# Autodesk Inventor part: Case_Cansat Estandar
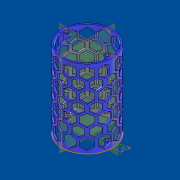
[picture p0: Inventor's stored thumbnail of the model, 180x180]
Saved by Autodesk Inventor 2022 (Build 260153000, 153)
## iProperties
Created: 2022-05
Part Number: Case_Cansat Estandar
Material: Genérico
Document SubType Name: Modeling
Designer: pined
Density: 1 g/cm^3
Appearance: Valor por defecto
Author: pined
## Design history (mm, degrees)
sketch "Boceto1"
  geometry: C1 r 32.5 at (0, 0); C2 r 30.5 at (0, 0); 1 further point
  constraints: 2 centre point, 2 coincident
  dimensions: "d0" = 65 diameter of C1; "d1" = 61 diameter of C2
extrude "Extrusión1" new body sketch "Boceto1" distance "d2" = 100; taper "d3" = 0 deg
node "Plano de trabajo1"
sketch "Boceto3"
  geometry: L1 (57, 0)-(53.5, -6.062); L2 (53.5, -6.062)-(46.5, -6.062); L3 (46.5, -6.062)-(43, 0); L4 (43, 0)-(46.5, 6.062); L5 (46.5, 6.062)-(53.5, 6.062); L6 (53.5, 6.062)-(57, 0); L7 (69.196, 0)-(72.696, 6.062); L8 (72.696, 6.062)-(79.696, 6.062); L9 (79.696, 6.062)-(83.196, 0); L10 (83.196, 0)-(79.696, -6.062); L11 (79.696, -6.062)-(72.696, -6.062); L12 (72.696, -6.062)-(69.196, 0); L13 (20.304, 6.062)-(16.804, 0); L14 (16.804, 0)-(20.304, -6.062); L15 (27.304, 6.062)-(20.304, 6.062); L16 (30.804, 0)-(27.304, 6.062); L17 (27.304, -6.062)-(30.804, 0); L18 (20.304, -6.062)-(27.304, -6.062); L19 (43, 0)-(46.5, -6.062); L20 (46.5, 6.062)-(43, 0); L21 (53.5, 6.062)-(46.5, 6.062); L22 (57, 0)-(53.5, 6.062); L23 (53.5, -6.062)-(57, 0); L24 (46.5, -6.062)-(53.5, -6.062); 5 further points
  constraints: 48 end point, 13 other
extrude "Extrusión2" cut sketch "Boceto3" distance "d29" = 10; taper "d30" = 0 deg
pattern_circular "Patrón circular1" dims angle "d32" = 360 deg
sketch "Boceto4"
  geometry: L1 (0, 0)-(-35, 0); L2 (0, 0)-(-36.309, -9.729); A1 r 32.5 centre (0, 0) between (-32.5, 0) and (-31.393, -8.412) reference; 1 further point
  constraints: 4 end point, 2 point on circle, 2 point on line, 1 horizontal
  dimensions: "d34" = 15 deg angle of L1 L2
node "Plano de trabajo3"
sketch "Boceto7"
  geometry: L1 (27.304, 2.408)-(20.304, 2.408) reference; L2 (20.304, -2.408)-(27.304, -2.408) reference; L3 (97, 0)-(93, -6.928); L4 (93, -6.928)-(85, -6.928); L5 (85, -6.928)-(81, 0); L6 (81, 0)-(85, 6.928); L7 (85, 6.928)-(93, 6.928); L8 (93, 6.928)-(97, 0); L9 (100, -32.5)-(100, 32.5) reference; L10 (19, 0)-(15, -6.928); L11 (15, -6.928)-(7, -6.928); L12 (7, -6.928)-(3, 0); L13 (3, 0)-(7, 6.928); L14 (7, 6.928)-(15, 6.928); L15 (15, 6.928)-(19, 0); L16 (0, 59.406)-(0, -64.57) reference; L17 (29, 0)-(33, 6.928); L18 (33, 6.928)-(41, 6.928); L19 (41, 6.928)-(45, 0); L20 (45, 0)-(41, -6.928); L21 (41, -6.928)-(33, -6.928); L22 (33, -6.928)-(29, 0); L23 (71, 0)-(67, -6.928); L24 (67, -6.928)-(59, -6.928); L25 (59, -6.928)-(55, 0); L26 (55, 0)-(59, 6.928); L27 (59, 6.928)-(67, 6.928); L28 (67, 6.928)-(71, 0); 13 further points; 4 other entities
  constraints: 48 end point, 56 other
  dimensions: "d37" = 8 distance of L3.start point (89, 0); "d38" = 3 distance from line of L9 L3.start; "d40" = 3 distance from line of L16 L12.end; "d41" = 8 distance of L12.end point (11, 0); "d42" = 8 distance of L19.end point (37, 0); "d44" = 8 distance of point (63, 0) L23.start
extrude "Extrusión3" cut sketch "Boceto7" distance "d45" = 10; taper "d46" = 0 deg
pattern_circular "Patrón circular2" dims angle "d48" = 360 deg
sketch "Boceto9"
  geometry: L1 (-30.5, 0)-(-26.5, 0); L2 (-26.5, 4)-(-30.237, 4); L3 (-26.5, -4)-(-30.237, -4); C1 r 1.5 at (-26.5, 0); A1 r 4 centre (-26.5, 0) between (-26.5, 4) and (-26.5, -4); A2 r 30.5 centre (0, 0) between (-30.5, 0) and (-30.237, -4) reference; A3 r 30.5 centre (0, 0) between (-30.237, 4) and (-30.237, -4); 3 further points
  constraints: 6 end point, 5 point on circle, 3 centre point, 3 coincident, 2 horizontal, 1 concentric
  dimensions: "d64" = 4 distance of L1.start L1.end; "d66" = 3 diameter of C1
extrude "Extrusión4" join sketch "Boceto9" distance "d52" = 5; taper "d53" = 0 deg
sketch "Boceto14"
  geometry: L1 (23.613, 0)-(25.057, 2.5); L2 (25.057, 2.5)-(27.943, 2.5); L3 (27.943, 2.5)-(29.387, 0); L4 (29.387, 0)-(27.943, -2.5); L5 (27.943, -2.5)-(25.057, -2.5); L6 (25.057, -2.5)-(23.613, 0); C1 r 1.5 at (26.5, 0) reference; 2 further points
  constraints: 12 end point, 1 coincident, 13 other
  dimensions: "d67" = 5 distance between parallel lines of L6 L3
extrude "Extrusión5" cut sketch "Boceto14" distance "d68" = 2.5; taper "d69" = 0 deg
pattern_circular "Patrón circular4" dims angle "d71" = 360 deg
sketch "Boceto15"
  geometry: L1 (29.387, 0)-(27.943, -2.5) reference; L2 (27.943, -2.5)-(25.057, -2.5) reference; L3 (25.057, -2.5)-(23.613, 0) reference; L4 (23.613, 0)-(25.057, 2.5) reference; L5 (25.057, 2.5)-(27.943, 2.5) reference; L6 (27.943, 2.5)-(29.387, 0) reference; L7 (30.237, 4)-(26.5, 4) reference; L8 (26.5, -4)-(30.237, -4) reference; L9 (-29.387, 0)-(-27.943, 2.5) reference; L10 (-27.943, 2.5)-(-25.057, 2.5) reference; L11 (-25.057, 2.5)-(-23.613, 0) reference; L12 (-23.613, 0)-(-25.057, -2.5) reference; L13 (-25.057, -2.5)-(-27.943, -2.5) reference; L14 (-27.943, -2.5)-(-29.387, 0) reference; L15 (-30.237, -4)-(-26.5, -4) reference; L16 (-26.5, 4)-(-30.237, 4) reference; L17 (26.5, -4)-(30.237, -4); L18 (26.5, 4)-(30.237, 4); L19 (31.358, 4)-(31.358, -4); L20 (30.237, 4)-(31.358, 4); L21 (30.237, -4)-(31.358, -4); C1 r 4 at (26.5, 0); C2 r 1.5 at (26.5, 0) reference; C3 r 1.5 at (26.5, 0); A1 r 4 centre (26.5, 0) between (26.5, 4) and (26.5, -4) reference; A2 r 30.5 centre (0, 0) between (30.237, -4) and (30.237, 4) reference; A3 r 4 centre (-26.5, 0) between (-26.5, -4) and (-26.5, 4) reference; A4 r 30.5 centre (0, 0) between (-30.237, 4) and (-30.237, -4) reference; A5 r 30.5 centre (0, 0) between (30.237, -4) and (30.237, 4); 1 further point
  constraints: 12 end point, 3 centre point, 3 coincident, 2 collinear, 2 concentric, 2 perpendicular, 2 point on circle, 2 tangent, 1 vertical
extrude "Extrusión6" join sketch "Boceto15" distance "d73" = 15; taper "d74" = 0 deg
sketch "Boceto16"
  geometry: L1 (23.613, 0)-(25.057, 2.5) reference; L2 (25.057, 2.5)-(27.943, 2.5) reference; L3 (27.943, 2.5)-(29.387, 0) reference; L4 (29.387, 0)-(27.943, -2.5) reference; L5 (27.943, -2.5)-(25.057, -2.5) reference; L6 (25.057, -2.5)-(23.613, 0) reference; L7 (25.057, -2.5)-(23.613, 0); L8 (23.613, 0)-(25.057, 2.5); L9 (25.057, 2.5)-(27.943, 2.5); L10 (27.943, 2.5)-(29.387, 0); L11 (29.387, 0)-(27.943, -2.5); L12 (27.943, -2.5)-(25.057, -2.5); C1 r 1.5 at (26.5, 0) reference; 2 further points
  constraints: 12 end point, 1 coincident, 13 other
extrude "Extrusión7" cut sketch "Boceto16" distance "d75" = 3; taper "d76" = 0 deg
pattern_circular "Patrón circular6" dims angle "d85" = 360 deg
sketch "Boceto21"
  geometry: L1 (0, 120)-(0, -20) reference; L2 (0, 100)-(-30.5, 100); L3 (-30.5, 100)-(-30.5, 85); L4 (0, 100)-(0, 64.522); L5 (-22.5, 100)-(-22.5, 85) reference; L6 (-22.5, 100)-(-22.5, 96.5); L7 (-22.5, 96.5)-(-30.5, 88.5); L8 (-9.917, 85)-(-22.5, 96.5); L9 (-30.5, 85)-(-9.917, 85); 3 further points
  constraints: 14 end point, 4 point on line, 2 horizontal, 1 perpendicular
  dimensions: "d88" = 30.5 distance of L2.start L2.end; "d89" = 3.5 distance of L5.start L6.end; "d90" = 45 deg angle of L7 L3
revolve "Revolución3" sketch "Boceto21" stored, may be unused: angle "d91" = 90 deg
sketch "Boceto24"
  geometry: L1 (-29.387, 0)-(-27.943, 2.5) reference; L2 (-27.943, 2.5)-(-25.057, 2.5) reference; L3 (-25.057, 2.5)-(-23.613, 0) reference; L4 (-23.613, 0)-(-25.057, -2.5) reference; L5 (-25.057, -2.5)-(-27.943, -2.5) reference; L6 (-27.943, -2.5)-(-29.387, 0) reference; L7 (30.237, 4)-(26.5, 4) reference; L8 (26.5, -4)-(30.237, -4) reference; L9 (-30.237, -4)-(-26.5, -4) reference; L10 (-26.5, 4)-(-30.237, 4) reference; L11 (29.387, 0)-(27.943, -2.5) reference; L12 (27.943, -2.5)-(25.057, -2.5) reference; L13 (25.057, -2.5)-(23.613, 0) reference; L14 (23.613, 0)-(25.057, 2.5) reference; L15 (25.057, 2.5)-(27.943, 2.5) reference; L16 (27.943, 2.5)-(29.387, 0) reference; L17 (-30.237, 4)-(-32.253, 4); L18 (-30.237, -4)-(-32.253, -4); L19 (30.237, 4)-(32.253, 4); L20 (30.237, -4)-(32.253, -4); C1 r 32.5 at (0, 0) reference; A1 r 30.5 centre (0, 0) between (30.237, 4) and (-30.237, 4) reference; A2 r 4 centre (26.5, 0) between (26.5, 4) and (26.5, -4) reference; A3 r 30.5 centre (0, 0) between (-30.237, -4) and (30.237, -4) reference; A4 r 4 centre (-26.5, 0) between (-26.5, -4) and (-26.5, 4) reference; A5 r 30.5 centre (0, 0) between (30.237, 4) and (-30.237, 4) reference; A6 r 32.5 centre (0, 0) between (-32.253, 4) and (-32.253, -4); A7 r 30.5 centre (0, 0) between (-30.237, 4) and (-30.237, -4); A8 r 30.5 centre (0, 0) between (30.237, -4) and (30.237, 4); A9 r 32.5 centre (0, 0) between (-32.253, 4) and (-32.253, -4); A10 r 32.5 centre (0, 0) between (32.253, -4) and (32.253, 4); 6 further points
  constraints: 10 point on circle, 8 end point, 5 centre point, 3 coincident, 3 horizontal, 1 parallel, 3 other
extrude "Extrusión9" join sketch "Boceto24" distance "d94" = 16.8; taper "d95" = 0 deg
node "Sólido1"
node "Contorno proyectado1"
node "Contorno proyectado2"
node "Contorno proyectado7"
other parameters: "d4" = 32.5
